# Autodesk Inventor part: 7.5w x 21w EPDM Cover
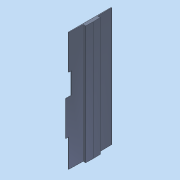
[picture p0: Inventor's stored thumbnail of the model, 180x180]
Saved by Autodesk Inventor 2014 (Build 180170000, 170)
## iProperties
Created: 2012-07
Part Number: 7.5w x 21w EPDM Cover
Document SubType Name: Modeling
Designer: david.appleford
Mass: 2.88978e+06 g
Surface Area: 5.78684e+06 cm^2
Volume: 2.88978e+06 cm^3
Density: 1 g/cm^3
Cost Center: £11,650.00
Description: 7.5w x 21w EPDM Cover
Material: Generic
Appearance: Slate Blue
Justset: False
Author: david.appleford
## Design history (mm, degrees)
sketch "Sketch1"
  geometry: L1 (-39, -8325)-(39, -8325) reference; L2 (39, -8325)-(39, -7105) reference; L3 (39, -7105)-(-39, -7105) reference; L4 (-39, -7105)-(-39, -8325) reference; L5 (571, -4665)-(649, -4665) reference; L6 (649, -4665)-(649, -1491) reference; L7 (649, -1491)-(571, -1491) reference; L8 (571, -1491)-(571, -4665) reference; L9 (-39, -1559)-(39, -1559) reference; L10 (39, -1559)-(39, 1559) reference; L11 (39, 1559)-(-39, 1559) reference; L12 (-39, 1559)-(-39, -1559) reference; L13 (-39, -7715)-(39, -7715) reference; L14 (39, -7715)-(39, -4541) reference; L15 (39, -4541)-(-39, -4541) reference; L16 (-39, -4541)-(-39, -7715) reference; L17 (49, -4615)-(571, -4615) reference; L18 (571, -1485)-(49, -1485) reference; L19 (-39, 1615)-(81.245, 1615); L20 (81.245, 1615)-(143.474, -1485); L21 (143.474, -1485)-(571, -1485); L22 (571, -1485)-(571, -1435); L23 (571, -1435)-(679, -1434.969); L24 (679, -1434.969)-(711.42, -3049.959); L25 (711.42, -3049.959)-(679, -4664.969); L26 (679, -4664.969)-(571, -4665); L27 (571, -4665)-(571, -4615); L28 (571, -4615)-(143.474, -4615); L29 (143.474, -4615)-(69, -8325); L30 (69, -8325)-(-39, -8325); L31 (-39, 1615)-(-39, -8325); L32 (174.876, -7715)-(-87.075, -7715); L33 (81.245, -7715)-(81.245, 2240.674); L34 (81.245, 2240.674)-(95.42, 2240.654); 1 further point
  constraints: 32 end point, 5 point on line, 2 parallel
  dimensions: "d1" = 108 distance from line of L29.end L31; "d2" = 3100 distance between parallel lines of L18 L19 (derived); "d3" = 3100 distance between parallel lines of L32 L17 (= d2); "d4" = 1.15 deg angle of L33 L29; "d5" = 1.15 deg angle of L33 L20 (= d4); "d6" = 1.15 deg angle of L6 L24; "d7" = 1.15 deg angle of L6 L25; "d8" = 1614.99993 distance from line of L24.end L23 (= d10); "d9" = 3229.99986 distance between parallel lines of L26 L23; "d10" = 1614.99993 distance from line of L24.end L26 (derived); "d11" = 108 distance from line of L25.end L27; "d12" = 108.00038 distance from line of L23.end L22 (derived); "d13" = 3710 distance between parallel lines of L30 L28 (derived)
  node "Reference2"
  node "Reference3"
  node "Reference5"
  node "Reference6"
  node "Reference7"
  node "Reference8"
workplane "Work Plane1"
extrude "Extrusion1" new body sketch "Sketch1" stored distance "d14" = 10; taper "d15" = 0 deg
sketch "Sketch2"
  geometry: L1 (-3716, 666)-(-7500, 666) reference; L2 (-7500, 610)-(-7500, 666) reference; L3 (-3716, 610)-(-7500, 610) reference; L4 (-3716, 610)-(-3716, 666) reference; L5 (-7444, 666)-(-7444, 1220) reference; L6 (-7500, 1220)-(-7444, 1220) reference; L7 (-7500, 666)-(-7500, 1220) reference; L8 (-7500, 666)-(-7444, 666) reference; L9 (-7444, 1276)-(-9884, 1276) reference; L10 (-9884, 1220)-(-9884, 1276) reference; L11 (-7444, 1220)-(-9884, 1220) reference; L12 (-7444, 1220)-(-7444, 1276) reference; L13 (-12195, 134)-(-12156, 134) reference; L14 (-12156, 1266)-(-12156, 134) reference; L15 (-12195, 1266)-(-12156, 1266) reference; L16 (-12195, 1266)-(-12195, 134) reference; L17 (-12256, 1220)-(-12256, 0) reference; L18 (-12200, 0)-(-12256, 0) reference; L19 (-12200, 1220)-(-12200, 0) reference; L20 (-12200, 1220)-(-12256, 1220) reference; L21 (-19644, 56)-(-19644, 610) reference; L22 (-19700, 610)-(-19644, 610) reference; L23 (-19700, 56)-(-19700, 610) reference; L24 (-19700, 56)-(-19644, 56) reference; L25 (-20786, 666)-(-20786, 610) reference; L26 (-19654, 610)-(-20786, 610) reference; L27 (-19654, 666)-(-19654, 610) reference; L28 (-19654, 666)-(-20786, 666) reference; L29 (-22016, 666)-(-25800, 666) reference; L30 (-25800, 610)-(-25800, 666) reference; L31 (-22016, 610)-(-25800, 610) reference; L32 (-22016, 610)-(-22016, 666) reference; L33 (0, 0)-(-25800, 0) reference; L34 (-25800, 9940)-(-25800, 0) reference; L35 (0, 0)-(0, 9940) reference; L36 (-12200, 0)-(0, 0); L37 (0, 0)-(0, 610); L38 (0, 610)-(-12200, 610); L39 (-12200, 610)-(-12200, 0); L40 (-7500, 610)-(-12200, 610); L41 (-12200, 610)-(-12200, 1220); L42 (-12200, 1220)-(-7500, 1220); L43 (-7500, 1220)-(-7500, 610); L44 (-19700, 0)-(-25800, 0); L45 (-25800, 0)-(-25800, 610); L46 (-25800, 610)-(-19700, 610); L47 (-19700, 610)-(-19700, 0); 1 further point
  constraints: 24 end point, 2 point on line
extrude "Extrusion2" cut sketch "Sketch2" stored distance "d16" = 10; taper "d17" = 0 deg
shell "Shell1" dims "d18" = 10
body "Solid1"
node "Reference9"
node "Reference10"
node "Reference11"
node "Reference12"
node "Reference13"
node "Reference14"
node "Reference15"
node "Reference16"
